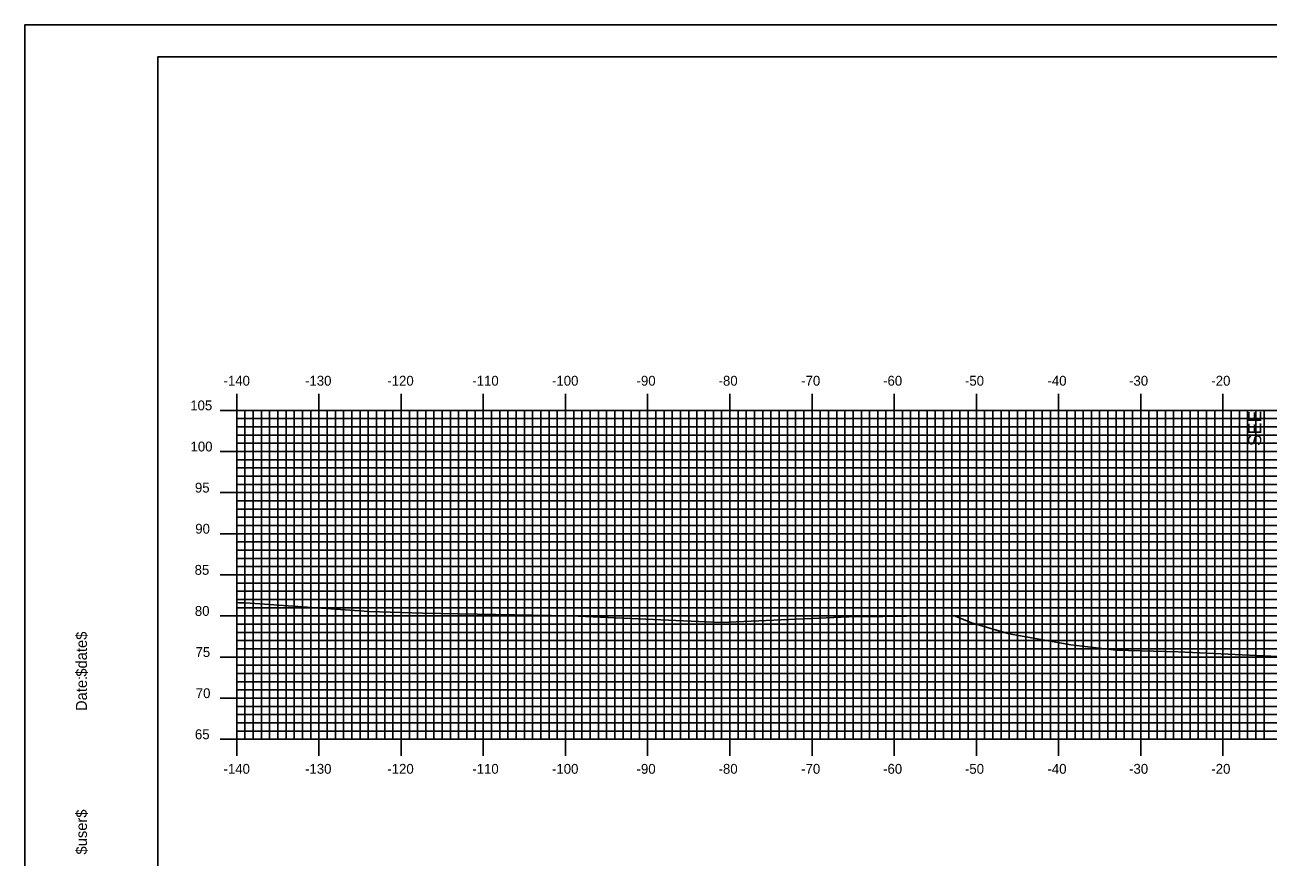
# Model space of a CAD drawing. Extents: x 852936 to 853279, y 364366 to 364586.
# Drawn here: x 852935.9 to 853087.2, y 364484.5 to 364585.7 of the extents above; entities that cross this region are included whole.
import ezdxf

# ---------------------------------------------------------------- set-up
doc = ezdxf.new("R2010")
doc.units = 0
for name, color, linetype in [('ANNOTATION', 7, 'Continuous'), ('BORDER', 7, 'Continuous'), ('H_V ANNOTATION', 7, 'Continuous'), ('MAJOR', 7, 'Continuous'), ('MINOR', 7, 'Continuous'), ('PLOT BOUNDARY', 7, 'Continuous'), ('S_Roadway_Centerline', 7, 'Continuous')]:
    doc.layers.add(name, color=color, linetype=linetype)

msp = doc.modelspace()

# ---------------------------------------------------------------- linework, layer by layer
at = {"layer": 'BORDER'}
msp.add_lwpolyline([(852952.09, 364371.79), (853272.09, 364371.79), (853272.09, 364581.79), (852952.09, 364581.79)], close=True, dxfattribs=at)
at = {"layer": 'MAJOR'}
for p, q in [((852961.69, 364540.79), (852961.69, 364538.79)), ((852971.69, 364540.79), (852971.69, 364538.79)), ((852981.69, 364540.79), (852981.69, 364538.79)), ((852991.69, 364540.79), (852991.69, 364538.79)), ((853001.69, 364540.79), (853001.69, 364538.79)), ((853011.69, 364540.79), (853011.69, 364538.79)), ((853021.69, 364540.79), (853021.69, 364538.79)), ((853031.69, 364540.79), (853031.69, 364538.79)), ((853041.69, 364540.79), (853041.69, 364538.79)), ((853051.69, 364540.79), (853051.69, 364538.79)), ((853061.69, 364540.79), (853061.69, 364538.79)), ((853071.69, 364540.79), (853071.69, 364538.79)), ((853081.69, 364540.79), (853081.69, 364538.79)), ((852959.69, 364538.79), (852961.69, 364538.79)), ((852961.69, 364538.79), (853241.69, 364538.79)), ((852961.69, 364498.79), (852961.69, 364538.79)), ((852961.69, 364498.79), (852961.69, 364538.79)), ((852961.69, 364538.79), (853241.69, 364538.79)), ((852971.69, 364498.79), (852971.69, 364538.79)), ((852981.69, 364498.79), (852981.69, 364538.79)), ((852991.69, 364498.79), (852991.69, 364538.79)), ((853001.69, 364498.79), (853001.69, 364538.79)), ((853011.69, 364498.79), (853011.69, 364538.79)), ((853021.69, 364498.79), (853021.69, 364538.79)), ((853031.69, 364498.79), (853031.69, 364538.79)), ((853041.69, 364498.79), (853041.69, 364538.79)), ((853051.69, 364498.79), (853051.69, 364538.79)), ((853061.69, 364498.79), (853061.69, 364538.79)), ((853071.69, 364498.79), (853071.69, 364538.79)), ((853081.69, 364498.79), (853081.69, 364538.79)), ((852959.69, 364533.79), (852961.69, 364533.79)), ((852961.69, 364533.79), (853241.69, 364533.79)), ((852959.69, 364528.79), (852961.69, 364528.79)), ((852961.69, 364528.79), (853241.69, 364528.79)), ((852959.69, 364523.79), (852961.69, 364523.79)), ((852961.69, 364523.79), (853241.69, 364523.79)), ((852959.69, 364518.79), (852961.69, 364518.79)), ((852961.69, 364518.79), (853241.69, 364518.79)), ((852959.69, 364513.79), (852961.69, 364513.79)), ((852961.69, 364513.79), (853241.69, 364513.79)), ((852959.69, 364508.79), (852961.69, 364508.79)), ((852961.69, 364508.79), (853241.69, 364508.79)), ((852959.69, 364503.79), (852961.69, 364503.79)), ((852961.69, 364503.79), (853241.69, 364503.79)), ((852959.69, 364498.79), (852961.69, 364498.79)), ((852961.69, 364498.79), (853241.69, 364498.79)), ((852961.69, 364498.79), (853241.69, 364498.79)), ((852961.69, 364496.78), (852961.69, 364498.79)), ((852971.69, 364496.78), (852971.69, 364498.79)), ((852981.69, 364496.78), (852981.69, 364498.79)), ((852991.69, 364496.78), (852991.69, 364498.79)), ((853001.69, 364496.78), (853001.69, 364498.79)), ((853011.69, 364496.78), (853011.69, 364498.79)), ((853021.69, 364496.78), (853021.69, 364498.79)), ((853031.69, 364496.78), (853031.69, 364498.79)), ((853041.69, 364496.78), (853041.69, 364498.79)), ((853051.69, 364496.78), (853051.69, 364498.79)), ((853061.69, 364496.78), (853061.69, 364498.79)), ((853071.69, 364496.78), (853071.69, 364498.79)), ((853081.69, 364496.78), (853081.69, 364498.79))]:
    msp.add_line(p, q, dxfattribs=at)
at = {"layer": 'MINOR'}
for p, q in [((852961.69, 364537.79), (853241.69, 364537.79)), ((852961.69, 364537.79), (852963.7, 364537.79)), ((852962.69, 364498.79), (852962.69, 364538.79)), ((852963.69, 364498.79), (852963.69, 364538.79)), ((852964.69, 364498.79), (852964.69, 364538.79)), ((852965.69, 364498.79), (852965.69, 364538.79)), ((852966.69, 364498.79), (852966.69, 364538.79)), ((852967.69, 364498.79), (852967.69, 364538.79)), ((852968.69, 364498.79), (852968.69, 364538.79)), ((852969.69, 364498.79), (852969.69, 364538.79)), ((852970.69, 364498.79), (852970.69, 364538.79)), ((852972.69, 364498.79), (852972.69, 364538.79)), ((852973.69, 364498.79), (852973.69, 364538.79)), ((852974.69, 364498.79), (852974.69, 364538.79)), ((852975.69, 364498.79), (852975.69, 364538.79)), ((852976.69, 364498.79), (852976.69, 364538.79)), ((852977.69, 364498.79), (852977.69, 364538.79)), ((852978.69, 364498.79), (852978.69, 364538.79)), ((852979.69, 364498.79), (852979.69, 364538.79)), ((852980.69, 364498.79), (852980.69, 364538.79)), ((852982.69, 364498.79), (852982.69, 364538.79)), ((852983.69, 364498.79), (852983.69, 364538.79)), ((852984.69, 364498.79), (852984.69, 364538.79)), ((852985.69, 364498.79), (852985.69, 364538.79)), ((852986.69, 364498.79), (852986.69, 364538.79)), ((852987.69, 364498.79), (852987.69, 364538.79)), ((852988.69, 364498.79), (852988.69, 364538.79)), ((852989.69, 364498.79), (852989.69, 364538.79)), ((852990.69, 364498.79), (852990.69, 364538.79)), ((852992.69, 364498.79), (852992.69, 364538.79)), ((852993.69, 364498.79), (852993.69, 364538.79)), ((852994.69, 364498.79), (852994.69, 364538.79)), ((852995.69, 364498.79), (852995.69, 364538.79)), ((852996.69, 364498.79), (852996.69, 364538.79)), ((852997.69, 364498.79), (852997.69, 364538.79)), ((852998.69, 364498.79), (852998.69, 364538.79)), ((852999.69, 364498.79), (852999.69, 364538.79)), ((853000.69, 364498.79), (853000.69, 364538.79)), ((853002.69, 364498.79), (853002.69, 364538.79)), ((853003.69, 364498.79), (853003.69, 364538.79)), ((853004.69, 364498.79), (853004.69, 364538.79)), ((853005.69, 364498.79), (853005.69, 364538.79)), ((853006.69, 364498.79), (853006.69, 364538.79)), ((853007.69, 364498.79), (853007.69, 364538.79)), ((853008.69, 364498.79), (853008.69, 364538.79)), ((853009.69, 364498.79), (853009.69, 364538.79)), ((853010.69, 364498.79), (853010.69, 364538.79)), ((853012.69, 364498.79), (853012.69, 364538.79)), ((853013.69, 364498.79), (853013.69, 364538.79)), ((853014.69, 364498.79), (853014.69, 364538.79)), ((853015.69, 364498.79), (853015.69, 364538.79)), ((853016.69, 364498.79), (853016.69, 364538.79)), ((853017.69, 364498.79), (853017.69, 364538.79)), ((853018.69, 364498.79), (853018.69, 364538.79)), ((853019.69, 364498.79), (853019.69, 364538.79)), ((853020.69, 364498.79), (853020.69, 364538.79)), ((853022.69, 364498.79), (853022.69, 364538.79)), ((853023.69, 364498.79), (853023.69, 364538.79)), ((853024.69, 364498.79), (853024.69, 364538.79)), ((853025.69, 364498.79), (853025.69, 364538.79)), ((853026.69, 364498.79), (853026.69, 364538.79)), ((853027.69, 364498.79), (853027.69, 364538.79)), ((853028.69, 364498.79), (853028.69, 364538.79)), ((853029.69, 364498.79), (853029.69, 364538.79)), ((853030.69, 364498.79), (853030.69, 364538.79)), ((853032.69, 364498.79), (853032.69, 364538.79)), ((853033.69, 364498.79), (853033.69, 364538.79)), ((853034.69, 364498.79), (853034.69, 364538.79)), ((853035.69, 364498.79), (853035.69, 364538.79)), ((853036.69, 364498.79), (853036.69, 364538.79)), ((853037.69, 364498.79), (853037.69, 364538.79)), ((853038.69, 364498.79), (853038.69, 364538.79)), ((853039.69, 364498.79), (853039.69, 364538.79)), ((853040.69, 364498.79), (853040.69, 364538.79)), ((853042.69, 364498.79), (853042.69, 364538.79)), ((853043.69, 364498.79), (853043.69, 364538.79)), ((853044.69, 364498.79), (853044.69, 364538.79)), ((853045.69, 364498.79), (853045.69, 364538.79)), ((853046.69, 364498.79), (853046.69, 364538.79)), ((853047.69, 364498.79), (853047.69, 364538.79)), ((853048.69, 364498.79), (853048.69, 364538.79)), ((853049.69, 364498.79), (853049.69, 364538.79)), ((853050.69, 364498.79), (853050.69, 364538.79)), ((853052.69, 364498.79), (853052.69, 364538.79)), ((853053.69, 364498.79), (853053.69, 364538.79)), ((853054.69, 364498.79), (853054.69, 364538.79)), ((853055.69, 364498.79), (853055.69, 364538.79)), ((853056.69, 364498.79), (853056.69, 364538.79)), ((853057.69, 364498.79), (853057.69, 364538.79)), ((853058.69, 364498.79), (853058.69, 364538.79)), ((853059.69, 364498.79), (853059.69, 364538.79)), ((853060.69, 364498.79), (853060.69, 364538.79)), ((853062.69, 364498.79), (853062.69, 364538.79)), ((853063.69, 364498.79), (853063.69, 364538.79)), ((853064.69, 364498.79), (853064.69, 364538.79)), ((853065.69, 364498.79), (853065.69, 364538.79)), ((853066.69, 364498.79), (853066.69, 364538.79)), ((853067.69, 364498.79), (853067.69, 364538.79)), ((853068.69, 364498.79), (853068.69, 364538.79)), ((853069.69, 364498.79), (853069.69, 364538.79)), ((853070.69, 364498.79), (853070.69, 364538.79)), ((853072.69, 364498.79), (853072.69, 364538.79)), ((853073.69, 364498.79), (853073.69, 364538.79)), ((853074.69, 364498.79), (853074.69, 364538.79)), ((853075.69, 364498.79), (853075.69, 364538.79)), ((853076.69, 364498.79), (853076.69, 364538.79)), ((853077.69, 364498.79), (853077.69, 364538.79)), ((853078.69, 364498.79), (853078.69, 364538.79)), ((853079.69, 364498.79), (853079.69, 364538.79)), ((853080.69, 364498.79), (853080.69, 364538.79)), ((853082.69, 364498.79), (853082.69, 364538.79)), ((853083.69, 364498.79), (853083.69, 364538.79)), ((853084.69, 364498.79), (853084.69, 364538.79)), ((853085.69, 364498.79), (853085.69, 364538.79)), ((853086.69, 364498.79), (853086.69, 364538.79)), ((852961.69, 364536.79), (853241.69, 364536.79)), ((852961.69, 364536.79), (852963.7, 364536.79)), ((852961.69, 364535.79), (853241.69, 364535.79)), ((852961.69, 364535.79), (852963.7, 364535.79)), ((852961.69, 364534.79), (853241.69, 364534.79)), ((852961.69, 364534.79), (852963.7, 364534.79)), ((852961.69, 364532.79), (853241.69, 364532.79)), ((852961.69, 364532.79), (852963.7, 364532.79)), ((852961.69, 364531.79), (853241.69, 364531.79)), ((852961.69, 364531.79), (852963.7, 364531.79)), ((852961.69, 364530.79), (853241.69, 364530.79)), ((852961.69, 364530.79), (852963.7, 364530.79)), ((852961.69, 364529.79), (853241.69, 364529.79)), ((852961.69, 364529.79), (852963.7, 364529.79)), ((852961.69, 364527.79), (853241.69, 364527.79)), ((852961.69, 364527.79), (852963.7, 364527.79)), ((852961.69, 364526.79), (853241.69, 364526.79)), ((852961.69, 364526.79), (852963.7, 364526.79)), ((852961.69, 364525.79), (853241.69, 364525.79)), ((852961.69, 364525.79), (852963.7, 364525.79)), ((852961.69, 364524.79), (853241.69, 364524.79)), ((852961.69, 364524.79), (852963.7, 364524.79)), ((852961.69, 364522.79), (853241.69, 364522.79)), ((852961.69, 364522.79), (852963.7, 364522.79)), ((852961.69, 364521.79), (853241.69, 364521.79)), ((852961.69, 364521.79), (852963.7, 364521.79)), ((852961.69, 364520.79), (853241.69, 364520.79)), ((852961.69, 364520.79), (852963.7, 364520.79)), ((852961.69, 364519.79), (853241.69, 364519.79)), ((852961.69, 364519.79), (852963.7, 364519.79)), ((852961.69, 364517.79), (853241.69, 364517.79)), ((852961.69, 364517.79), (852963.7, 364517.79)), ((852961.69, 364516.79), (853241.69, 364516.79)), ((852961.69, 364516.79), (852963.7, 364516.79)), ((852961.69, 364515.79), (853241.69, 364515.79)), ((852961.69, 364515.79), (852963.7, 364515.79)), ((852961.69, 364514.79), (853241.69, 364514.79)), ((852961.69, 364514.79), (852963.7, 364514.79)), ((852961.69, 364512.79), (853241.69, 364512.79)), ((852961.69, 364512.79), (852963.7, 364512.79)), ((852961.69, 364511.79), (853241.69, 364511.79)), ((852961.69, 364511.79), (852963.7, 364511.79)), ((852961.69, 364510.79), (853241.69, 364510.79)), ((852961.69, 364510.79), (852963.7, 364510.79)), ((852961.69, 364509.79), (853241.69, 364509.79)), ((852961.69, 364509.79), (852963.7, 364509.79)), ((852961.69, 364507.79), (853241.69, 364507.79)), ((852961.69, 364507.79), (852963.7, 364507.79)), ((852961.69, 364506.79), (853241.69, 364506.79)), ((852961.69, 364506.79), (852963.7, 364506.79)), ((852961.69, 364505.79), (853241.69, 364505.79)), ((852961.69, 364505.79), (852963.7, 364505.79)), ((852961.69, 364504.79), (853241.69, 364504.79)), ((852961.69, 364504.79), (852963.7, 364504.79)), ((852961.69, 364502.79), (853241.69, 364502.79)), ((852961.69, 364502.79), (852963.7, 364502.79)), ((852961.69, 364501.79), (853241.69, 364501.79)), ((852961.69, 364501.79), (852963.7, 364501.79)), ((852961.69, 364500.79), (853241.69, 364500.79)), ((852961.69, 364500.79), (852963.7, 364500.79)), ((852961.69, 364499.79), (853241.69, 364499.79)), ((852961.69, 364499.79), (852963.7, 364499.79))]:
    msp.add_line(p, q, dxfattribs=at)
at = {"layer": 'PLOT BOUNDARY'}
msp.add_lwpolyline([(852935.9, 364365.67), (853275.9, 364365.67), (853275.9, 364585.67), (852935.9, 364585.67)], close=True, dxfattribs=at)
at = {"layer": 'S_Roadway_Centerline'}
msp.add_lwpolyline([(852961.69, 364515.4), (852961.96, 364515.39), (852962.77, 364515.37), (852977.77, 364514.32), (852984.31, 364514.13), (853002.17, 364513.8), (853002.22, 364513.81), (853002.3, 364513.8), (853020.65, 364513), (853036.17, 364513.66), (853040.3, 364513.73), (853048.93, 364513.82), (853051.09, 364512.96), (853055.69, 364511.6), (853063.2, 364510.29), (853068.71, 364509.64), (853076.23, 364509.4), (853090.13, 364508.79)], dxfattribs=at)

# ---------------------------------------------------------------- texts
at = {"layer": 'ANNOTATION'}
msp.add_text('SEE', height=1.6, rotation=90, dxfattribs=at).set_placement((853086.35, 364534.45))
at = {"layer": 'BORDER'}
for s, p in [('$date$', (852943.46, 364506.4)), ('Date:', (852943.46, 364502.22)), ('$user$', (852943.46, 364484.77))]:
    msp.add_text(s, height=1.339, rotation=90, dxfattribs=at).set_placement(p)
at = {"layer": 'H_V ANNOTATION'}
for s, p in [('-140', (852960.08, 364541.79)), ('-130', (852970, 364541.79)), ('-120', (852980.01, 364541.79)), ('-110', (852990.35, 364541.79)), ('-100', (853000.05, 364541.79)), ('-90', (853010.34, 364541.79)), ('-80', (853020.32, 364541.79)), ('-70', (853030.37, 364541.79)), ('-60', (853040.34, 364541.79)), ('-50', (853050.3, 364541.79)), ('-40', (853060.34, 364541.79)), ('-30', (853070.27, 364541.79)), ('-20', (853080.28, 364541.79)), ('105', (852956.03, 364538.79)), ('100', (852956.06, 364533.79)), ('95', (852956.6, 364528.79)), ('90', (852956.64, 364523.79)), ('85', (852956.56, 364518.79)), ('80', (852956.59, 364513.79)), ('75', (852956.67, 364508.79)), ('70', (852956.7, 364503.79)), ('65', (852956.6, 364498.79)), ('-140', (852960.08, 364494.59)), ('-130', (852970, 364494.59)), ('-120', (852980.01, 364494.59)), ('-110', (852990.35, 364494.59)), ('-100', (853000.05, 364494.59)), ('-90', (853010.34, 364494.59)), ('-80', (853020.32, 364494.59)), ('-70', (853030.37, 364494.59)), ('-60', (853040.34, 364494.59)), ('-50', (853050.3, 364494.59)), ('-40', (853060.34, 364494.59)), ('-30', (853070.27, 364494.59)), ('-20', (853080.28, 364494.59))]:
    msp.add_text(s, height=1.2, dxfattribs=at).set_placement(p)
at = {"layer": 'MAJOR'}
msp.add_text('-', height=0.012, dxfattribs=at).set_placement((852961.68, 364498.79))

doc.saveas('drawing.dxf')
